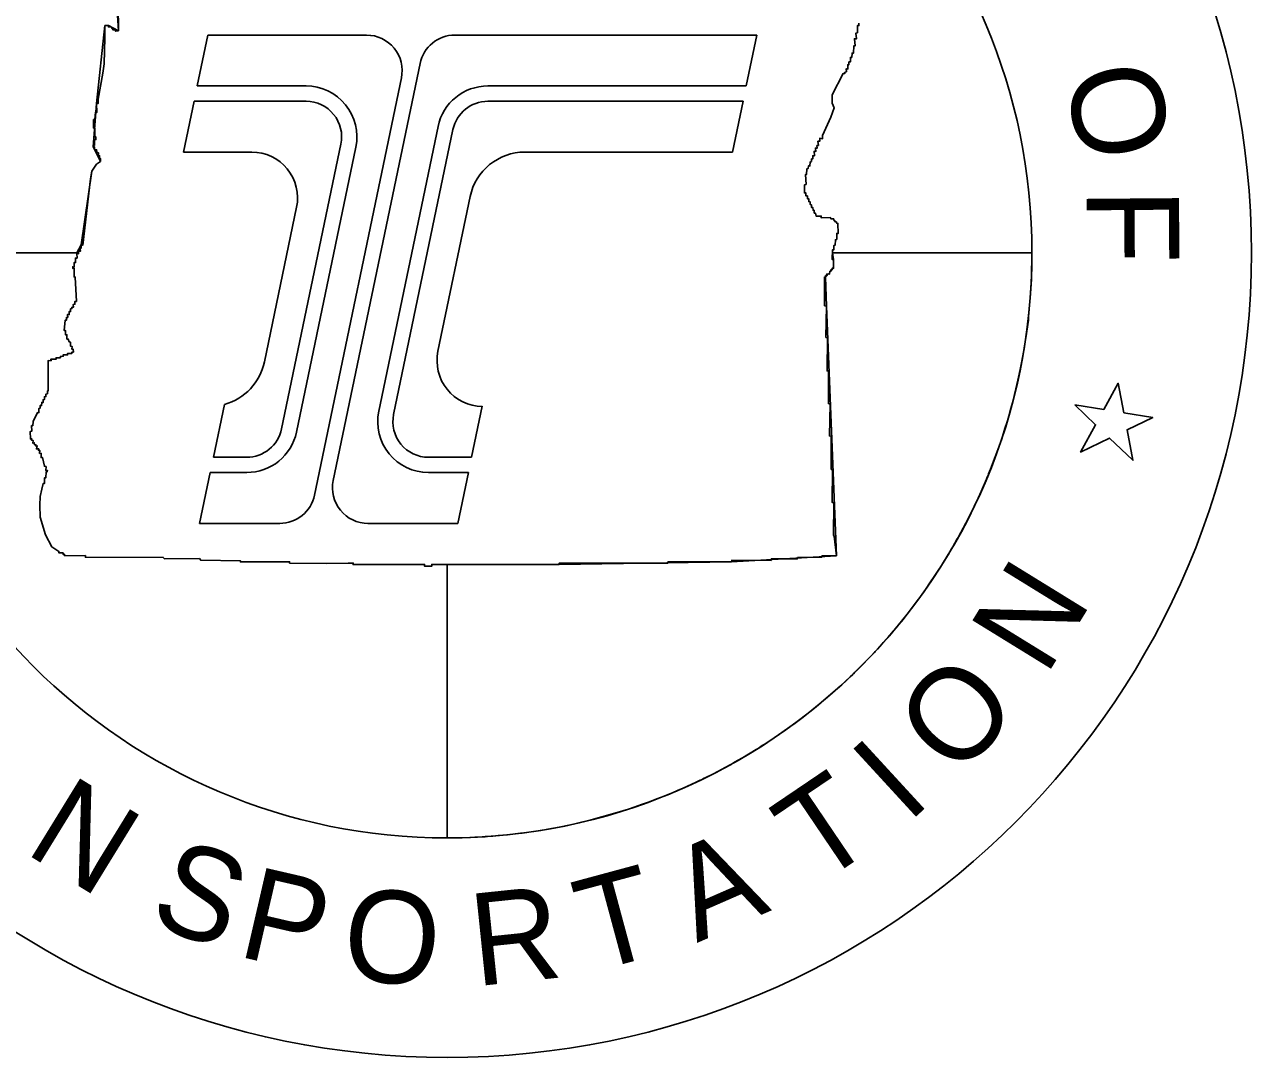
# Model space of a CAD drawing. Extents: x -1.2 to 17.3, y -1 to 2.5.
# Drawn here: x 0.0821 to 0.1583, y 1.8417 to 1.9058 of the extents above; entities that cross this region are included whole.
import ezdxf

# ---------------------------------------------------------------- set-up
doc = ezdxf.new("R2010")
doc.units = 0
doc.layers.add('P_ODOT_PLAN_TBlock', color=7, linetype='Continuous')

msp = doc.modelspace()

# ---------------------------------------------------------------- linework, layer by layer
at = {"layer": 'P_ODOT_PLAN_TBlock'}
for p, q in [((0.09279713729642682, 1.9020324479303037), (0.09345560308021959, 1.905192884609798)), ((0.09345560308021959, 1.905192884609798), (0.10332512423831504, 1.905192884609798)), ((0.10881333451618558, 1.905192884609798), (0.12758831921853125, 1.905192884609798)), ((0.12758831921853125, 1.905192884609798), (0.1269298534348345, 1.9020324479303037)), ((0.10124844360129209, 1.877516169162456), (0.10664756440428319, 1.903431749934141)), ((0.10549089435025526, 1.9025294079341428), (0.10009202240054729, 1.8766138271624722)), ((0.09956370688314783, 1.9020324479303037), (0.09279713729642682, 1.9020324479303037)), ((0.1269298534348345, 1.9020324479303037), (0.11086264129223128, 1.9020324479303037)), ((0.09194133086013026, 1.8979238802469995), (0.09259979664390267, 1.901084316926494)), ((0.09259979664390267, 1.901084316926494), (0.09956370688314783, 1.901084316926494)), ((0.11086289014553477, 1.901084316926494), (0.12673226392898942, 1.901084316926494)), ((0.12673226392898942, 1.901084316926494), (0.12607379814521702, 1.8979238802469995)), ((0.10776864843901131, 1.8995165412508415), (0.10408163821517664, 1.8818180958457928)), ((0.10500986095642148, 1.8816247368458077), (0.10869712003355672, 1.8993231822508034)), ((0.10172947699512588, 1.898420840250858), (0.09804246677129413, 1.8807223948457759)), ((0.09619099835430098, 1.8979238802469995), (0.09194133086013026, 1.8979238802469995)), ((0.09619099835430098, 1.8979238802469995), (0.09619099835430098, 1.8979238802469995)), ((0.09897068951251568, 1.8805290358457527), (0.10265769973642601, 1.8982274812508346)), ((0.12607379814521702, 1.8979238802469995), (0.11316926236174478, 1.8979238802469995)), ((0.10976594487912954, 1.8951563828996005), (0.1077636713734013, 1.8855461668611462)), ((0.09697364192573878, 1.8848891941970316), (0.09897566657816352, 1.8944994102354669)), ((0.09380175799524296, 1.8789612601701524), (0.09448685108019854, 1.8822498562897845)), ((0.11051573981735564, 1.8821284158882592), (0.10985578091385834, 1.8789612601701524)), ((0.09587669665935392, 1.8789612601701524), (0.09380175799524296, 1.8789612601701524)), ((0.10985578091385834, 1.8789612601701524), (0.10717563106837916, 1.8789612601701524)), ((0.09294570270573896, 1.8748526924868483), (0.09360416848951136, 1.8780131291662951)), ((0.09360416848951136, 1.8780131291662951), (0.09587669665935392, 1.8780131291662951)), ((0.10717563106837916, 1.8780131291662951), (0.1096581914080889, 1.8780131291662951)), ((0.1096581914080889, 1.8780131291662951), (0.10899997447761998, 1.8748526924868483)), ((0.09792625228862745, 1.8748526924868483), (0.09294570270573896, 1.8748526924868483)), ((0.10899997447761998, 1.8748526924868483), (0.10341421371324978, 1.8748526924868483))]:
    msp.add_line(p, q, dxfattribs=at)
for points in [[(0.08779376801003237, 1.9070446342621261), (0.08789920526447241, 1.9054619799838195), (0.08728240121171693, 1.9057848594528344), (0.08706220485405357, 1.9057864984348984), (0.08653976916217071, 1.9009404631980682), (0.08633221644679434, 1.8982467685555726), (0.08678186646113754, 1.8973430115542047), (0.08653639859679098, 1.8971729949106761), (0.08624057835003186, 1.8967322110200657), (0.08557892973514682, 1.8921601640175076), (0.08532195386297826, 1.8916666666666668), (0.07197577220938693, 1.8916666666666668)], [(0.13393565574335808, 1.9059453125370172), (0.13392985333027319, 1.9057813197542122), (0.1338355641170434, 1.9057856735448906), (0.13383500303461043, 1.9053353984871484), (0.13374484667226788, 1.9053220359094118), (0.13378491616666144, 1.9049679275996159), (0.1336513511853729, 1.9049645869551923), (0.13370143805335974, 1.904533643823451), (0.13361019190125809, 1.9045236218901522), (0.13359124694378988, 1.9040659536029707), (0.13350442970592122, 1.9040759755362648), (0.1334910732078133, 1.9038087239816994), (0.13340091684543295, 1.9038087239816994), (0.13341093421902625, 1.9035347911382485), (0.1333140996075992, 1.9035247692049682), (0.1333140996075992, 1.903351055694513), (0.13324063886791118, 1.903351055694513), (0.13324397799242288, 1.903083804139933), (0.13314714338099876, 1.9031038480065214), (0.13315048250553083, 1.9029167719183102), (0.13305933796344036, 1.9028900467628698), (0.13305698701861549, 1.9028165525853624), (0.1329534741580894, 1.9028165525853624), (0.13226071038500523, 1.9014800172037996), (0.13226071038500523, 1.9009614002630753), (0.13238510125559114, 1.9006709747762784), (0.13217778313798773, 1.900090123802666), (0.13167347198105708, 1.8989559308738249), (0.13167637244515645, 1.8987528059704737), (0.1315009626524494, 1.898784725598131), (0.13149654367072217, 1.8985990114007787), (0.13138342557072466, 1.8985990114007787), (0.13141243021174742, 1.8983378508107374), (0.13131671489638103, 1.8983262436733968), (0.1313283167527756, 1.8981637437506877), (0.13122680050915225, 1.8981695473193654), (0.13124420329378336, 1.8979577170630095), (0.13115760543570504, 1.8979838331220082), (0.131162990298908, 1.8976965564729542), (0.13106147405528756, 1.8976994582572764), (0.13107597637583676, 1.8975079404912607), (0.13098896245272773, 1.8975018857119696), (0.13098026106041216, 1.8973454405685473), (0.13089324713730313, 1.897301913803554), (0.13089034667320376, 1.8970697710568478), (0.1307920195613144, 1.8970697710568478), (0.13077341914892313, 1.896898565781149), (0.1306940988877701, 1.8968862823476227), (0.13067624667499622, 1.896536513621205), (0.13060596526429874, 1.896527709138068), (0.13064472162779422, 1.895914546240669), (0.13054808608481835, 1.8958850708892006), (0.1305395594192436, 1.8953828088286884), (0.13064187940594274, 1.8953856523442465), (0.13063903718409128, 1.8952036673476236), (0.13072714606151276, 1.8951979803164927), (0.13072654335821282, 1.8950270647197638), (0.13082093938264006, 1.8950131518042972), (0.13081404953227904, 1.8948504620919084), (0.13089918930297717, 1.894836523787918), (0.13089454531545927, 1.8946677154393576), (0.13098123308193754, 1.8946553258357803), (0.13099361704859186, 1.8944803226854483), (0.13106482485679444, 1.8944865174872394), (0.13108649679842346, 1.8943068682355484), (0.1311530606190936, 1.894303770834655), (0.1311530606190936, 1.8941365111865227), (0.13123665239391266, 1.8941225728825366), (0.13126910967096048, 1.8939472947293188), (0.13159034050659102, 1.893943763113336), (0.13158681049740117, 1.8938342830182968), (0.13217279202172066, 1.893859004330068), (0.13219397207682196, 1.8937742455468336), (0.1323669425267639, 1.8937742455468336), (0.13237400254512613, 1.8936859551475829), (0.13244813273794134, 1.8936413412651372), (0.13244107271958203, 1.8935967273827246), (0.13253638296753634, 1.8935870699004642), (0.1325505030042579, 1.8934987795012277), (0.1326211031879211, 1.8934881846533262), (0.13263169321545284, 1.8928630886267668), (0.1325505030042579, 1.89286662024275), (0.13255403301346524, 1.8925028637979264), (0.13246931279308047, 1.8924816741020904), (0.13245166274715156, 1.892132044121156), (0.132377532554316, 1.8921257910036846), (0.132377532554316, 1.891860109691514), (0.13229634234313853, 1.8918565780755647), (0.13227014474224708, 1.8912429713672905), (0.13235665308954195, 1.8912542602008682), (0.1323528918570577, 1.8907011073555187), (0.13226826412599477, 1.8907011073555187), (0.13227014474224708, 1.8906089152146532), (0.1321949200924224, 1.8906089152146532), (0.13218739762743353, 1.8905186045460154), (0.13211593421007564, 1.8905069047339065), (0.1321046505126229, 1.8903398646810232), (0.13194103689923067, 1.8903524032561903), (0.13195420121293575, 1.8902495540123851), (0.13185640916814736, 1.890245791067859), (0.13185264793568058, 1.890161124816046), (0.13178494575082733, 1.8901648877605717), (0.13179568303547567, 1.8893368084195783), (0.1318011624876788, 1.8883774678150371), (0.13191623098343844, 1.8883500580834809), (0.13187787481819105, 1.8864039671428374), (0.13198198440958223, 1.8863765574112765), (0.13195067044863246, 1.8843237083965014), (0.13203766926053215, 1.8843411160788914), (0.13203766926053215, 1.8822968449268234), (0.1321351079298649, 1.8822591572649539), (0.1321007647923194, 1.8802855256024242), (0.1322121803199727, 1.8802737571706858), (0.13220727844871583, 1.8782101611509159), (0.13228617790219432, 1.8782064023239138), (0.13226363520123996, 1.876169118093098), (0.1323763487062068, 1.876116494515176), (0.13236132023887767, 1.8741243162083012), (0.13238946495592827, 1.8740566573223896), (0.13252937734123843, 1.8728386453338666), (0.13163530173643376, 1.872830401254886), (0.13161882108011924, 1.8727520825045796), (0.1301232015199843, 1.872731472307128), (0.13009848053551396, 1.872649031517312), (0.12848749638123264, 1.8726572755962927), (0.12846689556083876, 1.872550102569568), (0.12602292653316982, 1.8725647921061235), (0.12600616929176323, 1.8724683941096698), (0.12206402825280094, 1.8724642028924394), (0.1220514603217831, 1.8723761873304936), (0.11530273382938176, 1.872387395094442), (0.11528395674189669, 1.8722887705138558), (0.10833918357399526, 1.8723013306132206), (0.10737683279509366, 1.8722998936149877), (0.10738401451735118, 1.8721993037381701), (0.10691720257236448, 1.8722036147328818), (0.10692869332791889, 1.8722998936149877), (0.10248538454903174, 1.872296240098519), (0.10249595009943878, 1.872386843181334), (0.10217143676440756, 1.8723853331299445), (0.10081865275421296, 1.8723699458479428), (0.09853556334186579, 1.872381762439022), (0.09854343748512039, 1.872472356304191), (0.09548490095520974, 1.8724605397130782), (0.09549839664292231, 1.8725235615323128), (0.09301604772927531, 1.8725617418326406), (0.09293191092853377, 1.872662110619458), (0.09077138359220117, 1.872656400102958), (0.09069049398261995, 1.8727347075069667), (0.08584855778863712, 1.8727490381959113), (0.08584719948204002, 1.8728476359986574), (0.08455001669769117, 1.8728428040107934), (0.0845513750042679, 1.8729363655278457), (0.0844576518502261, 1.872925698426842), (0.08446308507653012, 1.8730181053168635), (0.08420229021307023, 1.8730208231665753), (0.08420229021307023, 1.8731105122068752), (0.08376467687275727, 1.8733880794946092), (0.08336960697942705, 1.874138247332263), (0.08303097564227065, 1.8752308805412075), (0.0830229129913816, 1.875977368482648), (0.08303782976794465, 1.8765144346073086), (0.08313126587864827, 1.8769719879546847), (0.0832247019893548, 1.8773311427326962), (0.0832970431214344, 1.877324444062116), (0.08331076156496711, 1.8776902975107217), (0.083377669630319, 1.8776793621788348), (0.08339927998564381, 1.8780469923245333), (0.08346635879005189, 1.878049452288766), (0.0834927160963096, 1.8781330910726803), (0.08339682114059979, 1.8781330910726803), (0.08340173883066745, 1.8783864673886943), (0.08330092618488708, 1.8784012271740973), (0.08319016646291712, 1.878942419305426), (0.08309684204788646, 1.878937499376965), (0.08309438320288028, 1.879205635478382), (0.08300094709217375, 1.8792031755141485), (0.08301815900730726, 1.8793802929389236), (0.08292226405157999, 1.8793876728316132), (0.08294685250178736, 1.8794836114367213), (0.08279983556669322, 1.8794820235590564), (0.08285833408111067, 1.8796631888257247), (0.08276981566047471, 1.8796582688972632), (0.08276612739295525, 1.8797492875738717), (0.08267392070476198, 1.879736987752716), (0.08266900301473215, 1.8798624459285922), (0.0825854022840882, 1.8798353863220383), (0.08259769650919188, 1.8800125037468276), (0.08250180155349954, 1.8800149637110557), (0.08251901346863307, 1.8801035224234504), (0.08242557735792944, 1.8801059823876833), (0.0824206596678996, 1.880568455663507), (0.08251409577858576, 1.8805782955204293), (0.08249934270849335, 1.8809325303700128), (0.08257949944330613, 1.880915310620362), (0.08259277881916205, 1.8811760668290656), (0.08286350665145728, 1.8817372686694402), (0.08295679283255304, 1.8817317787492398), (0.08295313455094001, 1.8819952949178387), (0.08302630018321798, 1.8820044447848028), (0.08303727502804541, 1.8821801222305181), (0.08312690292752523, 1.8821709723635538), (0.0831360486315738, 1.8823649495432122), (0.08321470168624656, 1.8823576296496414), (0.08321470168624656, 1.8825387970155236), (0.08330250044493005, 1.88254428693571), (0.08330432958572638, 1.882716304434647), (0.08339395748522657, 1.8827298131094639), (0.08339395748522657, 1.8828919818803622), (0.08348175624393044, 1.882908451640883), (0.08348175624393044, 1.8830731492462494), (0.08352678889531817, 1.8830873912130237), (0.08353164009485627, 1.884972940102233), (0.08371356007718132, 1.8849559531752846), (0.08370143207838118, 1.8850603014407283), (0.08403026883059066, 1.8850576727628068), (0.08402466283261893, 1.885141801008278), (0.08429188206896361, 1.8851474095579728), (0.08429188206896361, 1.8852296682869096), (0.08447501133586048, 1.8852371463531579), (0.08447501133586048, 1.8853268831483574), (0.08474409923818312, 1.885325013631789), (0.08473849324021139, 1.8854128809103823), (0.08501058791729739, 1.8854091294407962), (0.0850122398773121, 1.8855000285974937), (0.0851030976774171, 1.8854967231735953), (0.085096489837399, 1.885671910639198), (0.08501389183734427, 1.8856768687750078), (0.0850163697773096, 1.8858528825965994), (0.08492468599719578, 1.8858570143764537), (0.0849180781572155, 1.8861206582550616), (0.0848410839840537, 1.8861265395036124), (0.08477878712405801, 1.886300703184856), (0.08469423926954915, 1.8863068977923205), (0.0846957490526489, 1.8865735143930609), (0.08460667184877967, 1.8865735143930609), (0.08460969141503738, 1.886842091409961), (0.08451985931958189, 1.8868384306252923), (0.08458830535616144, 1.8874713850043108), (0.08467060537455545, 1.887475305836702), (0.0846686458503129, 1.8876537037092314), (0.0847548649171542, 1.8876517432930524), (0.08473898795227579, 1.8878349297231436), (0.08483912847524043, 1.8878305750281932), (0.08483619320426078, 1.8880108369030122), (0.08492339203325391, 1.8880094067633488), (0.08492339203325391, 1.8881938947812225), (0.08500630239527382, 1.8881967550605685), (0.08501344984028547, 1.8882811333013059), (0.08509778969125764, 1.8882797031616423), (0.08509207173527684, 1.8884599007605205), (0.08519499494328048, 1.8884699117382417), (0.08519356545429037, 1.8886443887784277), (0.0852864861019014, 1.8886458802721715), (0.08521916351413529, 1.8901612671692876), (0.08513885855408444, 1.8901676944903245), (0.08515491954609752, 1.890704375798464), (0.08506176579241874, 1.8906947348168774), (0.08506497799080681, 1.8907975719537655), (0.08514849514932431, 1.8907815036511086), (0.08515813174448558, 1.8910643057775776), (0.0852416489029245, 1.891061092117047), (0.08522558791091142, 1.891334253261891), (0.08532516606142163, 1.891340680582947), (0.08532195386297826, 1.8916138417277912), (0.08541831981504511, 1.8916009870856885), (0.08540868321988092, 1.891771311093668), (0.08553447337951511, 1.8917616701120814), (0.08550183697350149, 1.891964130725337), (0.08558350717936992, 1.8919448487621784), (0.08557892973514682, 1.8921601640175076), (0.0856817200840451, 1.8921312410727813), (0.08617134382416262, 1.8962725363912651), (0.08624057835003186, 1.8967322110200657), (0.08653639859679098, 1.8971729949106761), (0.08678186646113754, 1.8973430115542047), (0.08679445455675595, 1.897519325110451), (0.08672942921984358, 1.8975309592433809), (0.08672410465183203, 1.8977035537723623), (0.08664956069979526, 1.8977019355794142), (0.08665275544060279, 1.897884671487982), (0.08657501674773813, 1.897891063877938), (0.08653903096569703, 1.89806614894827), (0.08640889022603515, 1.8980669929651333), (0.08642273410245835, 1.8982425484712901), (0.08633221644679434, 1.8982467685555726), (0.08634073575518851, 1.8983387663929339), (0.08640995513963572, 1.898343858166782), (0.08641980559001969, 1.898697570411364), (0.0865034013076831, 1.8986986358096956), (0.08650047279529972, 1.8988669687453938), (0.08642486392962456, 1.898874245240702), (0.0864293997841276, 1.899402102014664), (0.086355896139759, 1.8994198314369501), (0.086355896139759, 1.8999486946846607), (0.08643529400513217, 1.8999528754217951), (0.08647392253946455, 1.9003999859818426), (0.0865627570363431, 1.900404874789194), (0.08653976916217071, 1.9009404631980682), (0.08663094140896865, 1.900938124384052), (0.08663249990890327, 1.9012069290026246), (0.08693443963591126, 1.9028220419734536), (0.08701248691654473, 1.9034096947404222), (0.08705708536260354, 1.9050198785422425), (0.08706220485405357, 1.9057864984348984), (0.08728240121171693, 1.9057848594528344), (0.08728005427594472, 1.9056979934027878), (0.08747824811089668, 1.9056947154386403), (0.08748152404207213, 1.9056127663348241), (0.08756014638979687, 1.9056078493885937), (0.08756178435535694, 1.9055193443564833), (0.0877321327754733, 1.9055209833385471), (0.08772721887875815, 1.9054324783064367), (0.08789920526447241, 1.9054619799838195), (0.08789042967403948, 1.9070446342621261)]]:
    msp.add_lwpolyline(points, dxfattribs=at)
for points in [[(0.14466957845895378, 1.8904250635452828), (0.14465289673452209, 1.8900057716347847), (0.14458713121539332, 1.8888648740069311), (0.1444793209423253, 1.887705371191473), (0.14446372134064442, 1.887483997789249), (0.1443032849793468, 1.8863745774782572), (0.1442900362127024, 1.8862826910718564), (0.14429024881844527, 1.886281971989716), (0.14428895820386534, 1.886272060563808), (0.14426732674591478, 1.8861331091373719), (0.1442442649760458, 1.885986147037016), (0.1441961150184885, 1.8856909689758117), (0.14416076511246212, 1.8854825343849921), (0.1441022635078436, 1.885151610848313), (0.14404030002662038, 1.88482068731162), (0.14395830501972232, 1.8844060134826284), (0.14386102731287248, 1.8839444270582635), (0.14375799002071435, 1.8834828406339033), (0.14360906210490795, 1.8828634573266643), (0.14351398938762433, 1.8824915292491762), (0.1433776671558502, 1.8819838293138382), (0.14324484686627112, 1.881518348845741), (0.14315998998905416, 1.8812279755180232), (0.14315954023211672, 1.8812264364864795), (0.1431549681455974, 1.8812107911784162), (0.14313968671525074, 1.8811600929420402), (0.1430100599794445, 1.8807401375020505), (0.1428062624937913, 1.8801130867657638), (0.1425653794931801, 1.8794179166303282), (0.14230424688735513, 1.8787158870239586), (0.14211247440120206, 1.878219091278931), (0.14199670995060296, 1.877931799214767), (0.14197745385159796, 1.8778846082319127), (0.14196233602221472, 1.877847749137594), (0.14194979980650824, 1.8778172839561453), (0.14194286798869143, 1.8778007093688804), (0.14194190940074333, 1.8777984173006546), (0.14193648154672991, 1.8777850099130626), (0.1419112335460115, 1.8777240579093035), (0.14185694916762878, 1.8775952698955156), (0.1415899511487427, 1.876974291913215), (0.14144459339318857, 1.8766495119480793), (0.14136189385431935, 1.8764746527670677), (0.14131490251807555, 1.8763673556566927), (0.14113617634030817, 1.8759878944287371), (0.14089917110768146, 1.8755011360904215), (0.14057204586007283, 1.8748582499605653), (0.14027285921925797, 1.8742961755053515), (0.14010190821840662, 1.8739853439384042), (0.1400447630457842, 1.8738830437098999), (0.13976166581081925, 1.8733874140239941), (0.13965387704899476, 1.8732032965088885), (0.1395348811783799, 1.8730029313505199), (0.13937640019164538, 1.8727405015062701), (0.13923167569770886, 1.8725052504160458), (0.13906927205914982, 1.8722456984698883), (0.13899924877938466, 1.8721353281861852), (0.13896208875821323, 1.872077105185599), (0.13893916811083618, 1.8720413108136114), (0.13873662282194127, 1.8717289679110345), (0.13826448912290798, 1.8710269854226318), (0.13820479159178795, 1.8709406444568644), (0.138065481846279, 1.8707385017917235), (0.1376591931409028, 1.8701728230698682), (0.1375392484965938, 1.8700128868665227), (0.1375094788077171, 1.869972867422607), (0.13724812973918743, 1.8696207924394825), (0.13667543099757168, 1.8688897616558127), (0.1365519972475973, 1.8687411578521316), (0.13641375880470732, 1.868572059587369), (0.1362392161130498, 1.8683614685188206), (0.1360850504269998, 1.8681778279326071), (0.1357326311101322, 1.8677679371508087), (0.13563482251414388, 1.867656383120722), (0.13544504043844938, 1.867442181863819), (0.13538214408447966, 1.8673709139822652), (0.1350790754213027, 1.8670377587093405), (0.13493775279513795, 1.8668860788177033), (0.1348933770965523, 1.866838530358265), (0.13465904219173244, 1.8665896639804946), (0.13432035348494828, 1.8662395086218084), (0.1340603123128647, 1.8659763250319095), (0.13391347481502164, 1.865830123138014), (0.13368444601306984, 1.8656053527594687), (0.13358810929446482, 1.8655119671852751), (0.13357182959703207, 1.865496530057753), (0.13354750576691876, 1.8654728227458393), (0.133382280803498, 1.8653147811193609), (0.1331527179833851, 1.8650991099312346), (0.1328627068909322, 1.8648304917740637), (0.1326073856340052, 1.86459968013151), (0.13204968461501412, 1.864110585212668), (0.13126426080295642, 1.8634525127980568), (0.1308889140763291, 1.8631514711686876), (0.13067344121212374, 1.8629823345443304), (0.13045677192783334, 1.8628145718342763), (0.12997049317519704, 1.8624484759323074), (0.12963895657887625, 1.8622056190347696), (0.12878233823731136, 1.8616050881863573), (0.12823526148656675, 1.8612400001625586), (0.12804632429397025, 1.861117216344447), (0.1279274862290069, 1.861040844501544), (0.12766458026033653, 1.8608742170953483), (0.12754831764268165, 1.8608011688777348), (0.12670280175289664, 1.8602909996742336), (0.1262053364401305, 1.8600050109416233), (0.1260188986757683, 1.8599004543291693), (0.1259817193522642, 1.859879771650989), (0.12551937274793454, 1.8596267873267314), (0.1250479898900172, 1.859379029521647), (0.12484702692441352, 1.85927577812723), (0.12440573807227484, 1.8590545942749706), (0.12427554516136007, 1.8589907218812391), (0.1241362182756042, 1.8589231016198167), (0.12408759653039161, 1.8588996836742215), (0.12406711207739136, 1.8588898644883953), (0.1240600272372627, 1.8588864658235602), (0.12381687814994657, 1.858771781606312), (0.12301425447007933, 1.8584050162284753), (0.12266028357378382, 1.858250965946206), (0.12239116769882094, 1.858136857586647), (0.12204799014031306, 1.857994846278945), (0.12137933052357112, 1.8577303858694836), (0.12090449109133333, 1.85755161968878), (0.12066537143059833, 1.8574644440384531), (0.12042524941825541, 1.857379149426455), (0.12001338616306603, 1.8572363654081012), (0.11959974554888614, 1.8570989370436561), (0.11876093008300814, 1.8568365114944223), (0.11729026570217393, 1.856429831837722), (0.11635534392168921, 1.856205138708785), (0.11599937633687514, 1.8561265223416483), (0.11530483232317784, 1.8559825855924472), (0.11460037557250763, 1.855853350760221), (0.11415091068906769, 1.8557775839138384), (0.11369949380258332, 1.8557072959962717), (0.11299220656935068, 1.855608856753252), (0.11289479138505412, 1.8555964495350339), (0.1120786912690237, 1.8555026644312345), (0.11150850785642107, 1.8554480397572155), (0.11117901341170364, 1.8554206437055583), (0.11114947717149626, 1.8554184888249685), (0.11107024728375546, 1.855412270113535), (0.11085035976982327, 1.8553963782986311), (0.11072834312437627, 1.8553880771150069), (0.11068176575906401, 1.8553850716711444), (0.11021302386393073, 1.855358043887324), (0.11004821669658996, 1.8553495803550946), (0.1097831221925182, 1.8553380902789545), (0.10927317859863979, 1.855320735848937), (0.10895562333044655, 1.8553142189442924), (0.10854567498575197, 1.8553095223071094), (0.10839961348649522, 1.8553091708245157), (0.1083333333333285, 1.8553091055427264), (0.1083333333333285, 1.8723013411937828), (0.11528395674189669, 1.8722887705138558), (0.12600616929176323, 1.8724683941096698), (0.13252937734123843, 1.8728386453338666), (0.13191623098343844, 1.8883500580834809), (0.13185264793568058, 1.890161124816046), (0.1323528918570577, 1.8907011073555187), (0.13235665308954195, 1.8912542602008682), (0.13228823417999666, 1.8916666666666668), (0.1446908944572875, 1.8916666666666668), (0.1446908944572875, 1.8915433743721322), (0.1446908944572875, 1.8913143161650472)], [(0.1473555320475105, 1.882209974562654), (0.14915565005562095, 1.8819248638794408), (0.1500540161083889, 1.8835643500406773), (0.15040178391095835, 1.8817274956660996), (0.15220190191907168, 1.8814423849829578), (0.15060114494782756, 1.880674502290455), (0.15096111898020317, 1.878773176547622), (0.1495136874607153, 1.880152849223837), (0.14771075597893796, 1.8792879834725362), (0.148640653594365, 1.8809850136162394)]]:
    msp.add_lwpolyline(points, close=True, dxfattribs=at)
for radius in [0.050000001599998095, 0.036357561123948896]:
    msp.add_circle((0.1083333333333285, 1.8916666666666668), radius, dxfattribs=at)
for centre, radius, start, end in [((0.10332519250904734, 1.9029804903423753), 0.002212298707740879, 348.23180555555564, 90.00000000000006), ((0.10881330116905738, 1.9029804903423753), 0.002212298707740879, 90.00000000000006, 168.2318055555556), ((0.09956378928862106, 1.8988719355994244), 0.003160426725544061, 348.23183055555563, 90.00000000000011), ((0.11086275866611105, 1.8988719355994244), 0.003160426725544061, 90.00000000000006, 168.23180000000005), ((0.09956380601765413, 1.8988719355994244), 0.002212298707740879, 348.23171111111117, 90.00000000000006), ((0.11086278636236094, 1.8988719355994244), 0.002212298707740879, 90.00000000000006, 168.23184166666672), ((0.09619107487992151, 1.8950794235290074), 0.002844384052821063, 348.2317944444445, 90.00000000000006), ((0.11316923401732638, 1.894447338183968), 0.00347646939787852, 90.00000000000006, 168.2318944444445), ((0.11054834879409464, 1.884966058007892), 0.0028443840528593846, 168.23179444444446, 269.30883611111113), ((0.09357014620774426, 1.8855981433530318), 0.0034764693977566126, 285.46915555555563, 348.23171111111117), ((0.10717563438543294, 1.8811735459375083), 0.003160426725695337, 168.23183055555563, 270.0000000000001), ((0.10717566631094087, 1.8811735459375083), 0.0022122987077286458, 168.2317944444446, 270.00000000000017), ((0.09587663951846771, 1.8811735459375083), 0.0022122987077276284, 270.00000000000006, 348.2317722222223), ((0.09587666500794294, 1.8811735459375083), 0.003160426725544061, 270.00000000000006, 348.2318), ((0.103414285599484, 1.877064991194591), 0.0022122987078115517, 168.2317694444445, 270.00000000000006), ((0.09792617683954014, 1.877064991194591), 0.00221229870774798, 270.00000000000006, 348.23175555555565)]:
    msp.add_arc(centre, radius, start, end, dxfattribs=at)

# ---------------------------------------------------------------- texts
for s, height, rotation, p in [('O', 0.005738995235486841, 281.0153190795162, (0.14668064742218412, 1.9028661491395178)), ('F', 0.005738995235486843, 270.4549130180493, (0.14808368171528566, 1.8956484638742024)), ('N', 0.005738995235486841, 58.37169331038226, (0.14554345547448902, 1.8652816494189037)), ('O', 0.005738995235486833, 47.81128724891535, (0.1400775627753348, 1.8589089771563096)), ('I', 0.005738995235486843, 42.57913222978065, (0.13695807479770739, 1.8561506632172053)), ('T', 0.005738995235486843, 34.07346227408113, (0.13139016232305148, 1.8523074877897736)), ('N', 0.005738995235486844, 328.40862769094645, (0.08197230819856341, 1.8544395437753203)), ('S', 0.005738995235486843, 339.5081090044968, (0.08963211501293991, 1.8500610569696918)), ('A', 0.005738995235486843, 23.606808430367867, (0.12385639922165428, 1.84877381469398)), ('P', 0.005738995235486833, 346.9746918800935, (0.09519724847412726, 1.8479836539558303)), ('T', 0.005738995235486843, 15.101138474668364, (0.11734149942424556, 1.8469496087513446)), ('O', 0.005738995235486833, 355.3787969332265, (0.1017227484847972, 1.8465328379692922)), ('R', 0.005738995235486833, 5.939202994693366, (0.11010648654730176, 1.846085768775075))]:
    msp.add_text(s, height=height, rotation=rotation, dxfattribs=at).set_placement(p)

doc.saveas('drawing.dxf')
